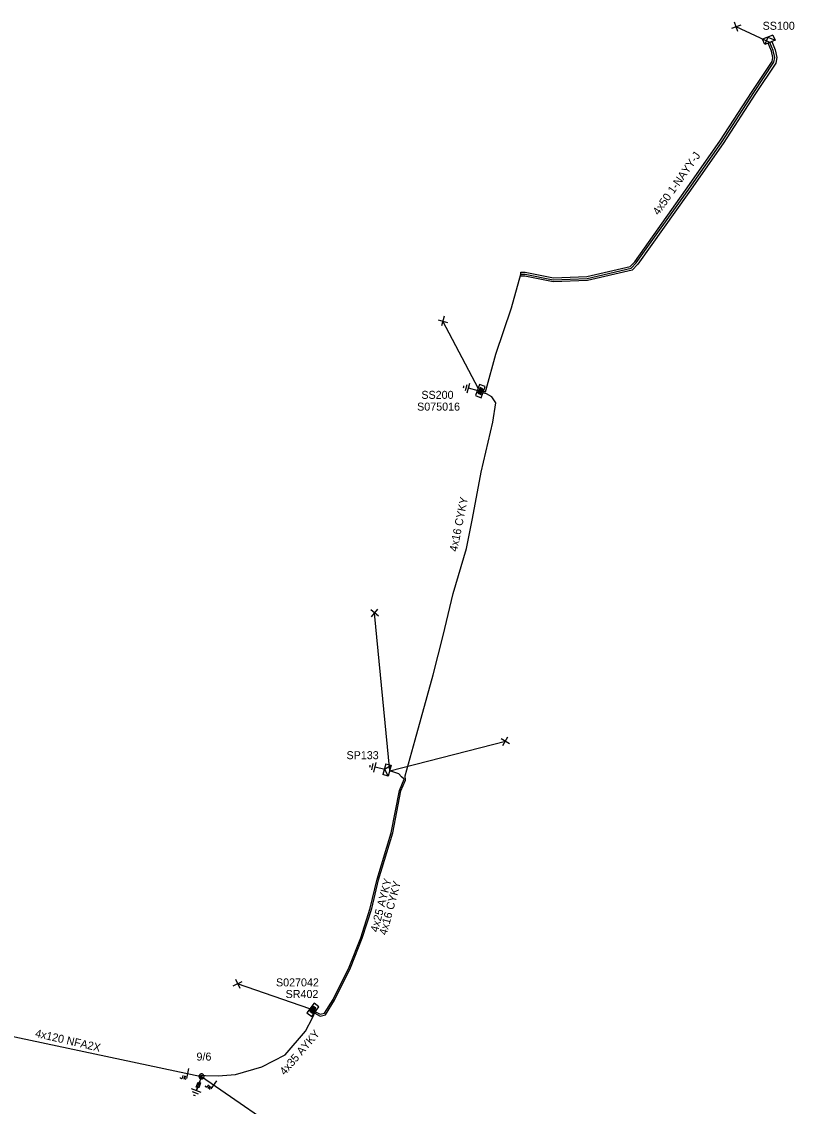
# Model space of a CAD drawing. Extents: x -788458 to -786145, y -1154772 to -1152372.
# Drawn here: x -786269.7 to -786173.2, y -1153537 to -1153401.5 of the extents above; entities that cross this region are included whole.
import ezdxf

# ---------------------------------------------------------------- set-up
doc = ezdxf.new("R2010")
doc.units = 0
for name, color, linetype in [('Vrstva 1', 7, 'Continuous'), ('Vrstva 12', 7, 'Continuous'), ('Vrstva 13', 7, 'Continuous'), ('Vrstva 14', 7, 'Continuous'), ('Vrstva 15', 7, 'Continuous'), ('Vrstva 16', 7, 'Continuous'), ('Vrstva 18', 7, 'Continuous'), ('Vrstva 2', 7, 'Continuous'), ('Vrstva 20', 7, 'Continuous'), ('Vrstva 28', 7, 'Continuous'), ('Vrstva 29', 7, 'Continuous'), ('Vrstva 30', 7, 'Continuous'), ('Vrstva 31', 7, 'Continuous'), ('Vrstva 33', 7, 'Continuous'), ('Vrstva 34', 7, 'Continuous'), ('Vrstva 5', 7, 'Continuous'), ('Vrstva 50', 7, 'Continuous'), ('Vrstva 51', 7, 'Continuous'), ('Vrstva 52', 7, 'Continuous'), ('Vrstva 54', 7, 'Continuous'), ('Vrstva 59', 7, 'Continuous'), ('Vrstva 6', 7, 'Continuous'), ('Vrstva 8', 7, 'Continuous'), ('Vrstva 9', 7, 'Continuous')]:
    doc.layers.add(name, color=color, linetype=linetype)

# ---------------------------------------------------------------- blocks, each defined once
blk = doc.blocks.new('NN440')
at = {"layer": 'Vrstva 2'}
for points in [[(0.63, 0), (0.63, 0.06), (0.62, 0.13), (0.6, 0.19), (0.58, 0.25), (0.55, 0.31), (0.51, 0.37), (0.47, 0.42), (0.42, 0.46), (0.37, 0.51), (0.32, 0.54), (0.26, 0.57), (0.2, 0.59), (0.13, 0.61), (0.07, 0.62), (0, 0.63), (-0.06, 0.62), (-0.13, 0.61), (-0.19, 0.59), (-0.26, 0.57), (-0.31, 0.54), (-0.37, 0.51), (-0.42, 0.46), (-0.47, 0.42), (-0.51, 0.37), (-0.54, 0.31), (-0.57, 0.25), (-0.6, 0.19), (-0.62, 0.13), (-0.63, 0.06), (-0.63, 0), (-0.63, -0.07), (-0.62, -0.14), (-0.6, -0.2), (-0.57, -0.26), (-0.54, -0.32), (-0.51, -0.37), (-0.47, -0.43), (-0.42, -0.47), (-0.37, -0.51), (-0.31, -0.55), (-0.26, -0.58), (-0.19, -0.6), (-0.13, -0.62), (-0.06, -0.63), (0, -0.63), (0.07, -0.63), (0.13, -0.62), (0.2, -0.6), (0.26, -0.58), (0.32, -0.55), (0.37, -0.51), (0.42, -0.47), (0.47, -0.43), (0.51, -0.37), (0.55, -0.32), (0.58, -0.26), (0.6, -0.2), (0.62, -0.14), (0.63, -0.07), (0.63, 0)], [(-0.63, 0), (0.63, 0)], [(-0.6, -0.18), (0.57, -0.18)], [(-0.51, -0.32), (0.5, -0.32)], [(-0.37, -0.47), (0.35, -0.47)]]:
    blk.add_lwpolyline(points, dxfattribs=at)
blk = doc.blocks.new('NN840')
at = {"layer": 'Vrstva 15'}
for points in [[(0, 0.62), (0, -0.63)], [(-0.75, -0.71), (-0.75, -0.66)], [(-0.73, -0.76), (-0.75, -0.71)], [(-0.66, -0.8), (-0.73, -0.76)], [(-0.63, -0.8), (-0.66, -0.8)], [(-0.56, -0.76), (-0.63, -0.8)], [(-0.54, -0.71), (-0.56, -0.76)], [(-0.54, -0.38), (-0.54, -0.71)], [(-0.33, -0.38), (-0.33, -0.8)], [(-0.33, -0.64), (-0.13, -0.38)], [(-0.26, -0.56), (-0.09, -0.8)]]:
    blk.add_lwpolyline(points, dxfattribs=at)
blk = doc.blocks.new('NN800')
at = {"layer": 'Vrstva 1'}
for points in [[(-0.44, 0.44), (0.44, -0.44)], [(-0.44, -0.44), (0.44, 0.44)]]:
    blk.add_lwpolyline(points, dxfattribs=at)
blk = doc.blocks.new('NN820')
at = {"layer": 'Vrstva 13'}
for points in [[(0, 0), (0, -1.05)], [(-0.16, -0.81), (0.16, -0.81)], [(-0.16, -1.47), (-0.16, -0.81)], [(0, -1.05), (-0.06, -0.93)], [(0, -1.05), (0.06, -0.93)], [(0.16, -0.81), (0.16, -1.47)], [(0.16, -1.47), (-0.16, -1.47)], [(0, -1.47), (0, -1.87)]]:
    blk.add_lwpolyline(points, dxfattribs=at)
blk = doc.blocks.new('NN620')
at = {"layer": 'Vrstva 8'}
for points in [[(0.75, 0), (-0.75, 0)], [(-0.75, 0), (-0.75, -0.75)], [(0.75, -0.75), (0.75, 0)], [(-0.75, -0.75), (0.75, -0.75)], [(0.37, -0.18), (-0.38, -0.18)], [(-0.38, -0.18), (-0.38, -0.56)], [(-0.38, -0.56), (0.37, -0.56)], [(0.32, -0.23), (-0.33, -0.23)], [(-0.33, -0.23), (-0.33, -0.51)], [(-0.33, -0.51), (0.32, -0.51)], [(0.27, -0.27), (-0.28, -0.27)], [(-0.28, -0.27), (-0.28, -0.46)], [(-0.28, -0.46), (0.27, -0.46)], [(0.23, -0.32), (-0.23, -0.32)], [(-0.23, -0.32), (-0.23, -0.42)], [(-0.23, -0.42), (0.23, -0.42)], [(-0.19, -0.37), (0.19, -0.37)], [(0.23, -0.42), (0.23, -0.32)], [(0.27, -0.46), (0.27, -0.27)], [(0.32, -0.51), (0.32, -0.23)], [(0.37, -0.56), (0.37, -0.18)]]:
    blk.add_lwpolyline(points, dxfattribs=at)
blk = doc.blocks.new('NN630')
at = {"layer": 'Vrstva 9'}
for points in [[(0, -0.7), (-0.7, 0)], [(-0.7, -0.7), (-0.7, 0), (0.7, 0), (0.7, -0.7)], [(-0.7, -0.7), (0.7, -0.7)], [(0, -0.7), (0.7, 0)]]:
    blk.add_lwpolyline(points, dxfattribs=at)
blk = doc.blocks.new('NN810')
at = {"layer": 'Vrstva 14'}
for points in [[(0, -0.64), (0, -1.89)], [(0.63, -1.89), (-0.62, -1.89)], [(0.39, -2.2), (-0.4, -2.2)], [(0, -2.52), (-0.12, -2.52)], [(0.14, -2.52), (0, -2.52)]]:
    blk.add_lwpolyline(points, dxfattribs=at)

msp = doc.modelspace()

# ---------------------------------------------------------------- linework, layer by layer
at = {"layer": 'Vrstva 20'}
msp.add_lwpolyline([(-786207.37, -1153432.81), (-786206.82, -1153432.83), (-786203.3, -1153433.53), (-786199.12, -1153433.36), (-786193.74, -1153432.11), (-786193.15, -1153431.52), (-786186.81, -1153422.6), (-786182.51, -1153416.47), (-786178.48, -1153410.24), (-786176, -1153406.5), (-786175.91, -1153406.02), (-786176.09, -1153405.23), (-786176.5, -1153404.21), (-786176.04, -1153404.03), (-786175.61, -1153405.07), (-786175.39, -1153406), (-786175.52, -1153406.7), (-786178.06, -1153410.52), (-786182.09, -1153416.75), (-786186.41, -1153422.88), (-786192.77, -1153431.84), (-786193.48, -1153432.57), (-786199.06, -1153433.86), (-786203.34, -1153434.03), (-786206.88, -1153433.33), (-786207.39, -1153433.31)], close=True, dxfattribs=at)
at = {"layer": 'Vrstva 5'}
for points in [[(-786212.05, -1153447.7), (-786211.78, -1153447.79), (-786211.7, -1153447.49), (-786210.5, -1153443.05), (-786208.55, -1153437.3), (-786207.38, -1153433.06), (-786206.85, -1153433.08), (-786203.32, -1153433.78), (-786199.09, -1153433.61), (-786193.61, -1153432.34), (-786192.96, -1153431.68), (-786186.61, -1153422.74), (-786182.3, -1153416.61), (-786178.27, -1153410.38), (-786175.76, -1153406.6), (-786175.65, -1153406.01), (-786175.85, -1153405.15), (-786176.27, -1153404.12)], [(-786233.25, -1153525.16), (-786233.12, -1153525.4), (-786232.45, -1153525.74), (-786231.77, -1153525.58), (-786230.66, -1153523.76), (-786228.65, -1153519.72), (-786227.18, -1153516.02), (-786226, -1153512.31), (-786225.14, -1153508.72), (-786223.38, -1153502.88), (-786222.35, -1153497.62), (-786221.78, -1153496.27), (-786221.81, -1153495.72), (-786220.58, -1153491.25), (-786218.33, -1153483.11), (-786217.07, -1153478.19), (-786215.84, -1153472.98), (-786214.15, -1153467.33), (-786213.4, -1153463.6), (-786212.33, -1153457.81), (-786210.87, -1153451.55), (-786210.5, -1153449.13), (-786211.01, -1153448.38), (-786211.67, -1153448.02), (-786212.11, -1153447.9)], [(-786247.26, -1153533.29), (-786247.3, -1153533.13), (-786246.75, -1153533.16), (-786245.18, -1153533.23), (-786243.03, -1153533.06), (-786239.71, -1153532.1), (-786236.8, -1153530.6), (-786234.28, -1153527.64), (-786233.38, -1153525.95), (-786233.18, -1153525.53), (-786233.33, -1153525.28)]]:
    msp.add_lwpolyline(points, dxfattribs=at)
at = {"layer": 'Vrstva 50'}
msp.add_lwpolyline([(-786381.77, -1153491.03), (-786354.19, -1153499.92), (-786327.4, -1153511.45), (-786300.99, -1153523.12), (-786278.65, -1153526.63), (-786247.26, -1153533.29)], dxfattribs=at)
at = {"layer": 'Vrstva 52'}
for points in [[(-786233.14, -1153525.01), (-786233.04, -1153525.22), (-786232.43, -1153525.52), (-786231.89, -1153525.4), (-786230.84, -1153523.66), (-786228.83, -1153519.64), (-786227.36, -1153515.96), (-786226.2, -1153512.25), (-786225.34, -1153508.66), (-786223.58, -1153502.84), (-786222.55, -1153497.56), (-786221.95, -1153496.16), (-786222.3, -1153495.85), (-786222.62, -1153495.5), (-786223.75, -1153495.1)], [(-786247.26, -1153533.29), (-786223.36, -1153549.79)]]:
    msp.add_lwpolyline(points, dxfattribs=at)
at = {"layer": 'Vrstva 59'}
for points in [[(-786176.27, -1153404.12), (-786180.47, -1153402.18)], [(-786212.68, -1153447.4), (-786217.12, -1153438.94)], [(-786223.75, -1153495.1), (-786225.64, -1153475.4)], [(-786223.75, -1153495.1), (-786209.31, -1153491.4)], [(-786233.72, -1153524.83), (-786242.76, -1153521.7)]]:
    msp.add_lwpolyline(points, dxfattribs=at)

# ---------------------------------------------------------------- block references
at = {"layer": 'Vrstva 13', "xscale": 0.5, "yscale": 0.5, "rotation": -13.03261396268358}
msp.add_blockref('NN440', (-786247.26, -1153533.29), dxfattribs=at)
at = {"layer": 'Vrstva 15'}
for p, rotation in [((-786212.08, -1153447.8), -105.18592123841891), ((-786223.75, -1153495.1), -102.95184169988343), ((-786247.26, -1153533.29), -20.32511953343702)]:
    msp.add_blockref('NN810', p, dxfattribs=dict(at, rotation=rotation))
at = {"layer": 'Vrstva 16', "rotation": -20.232686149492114}
msp.add_blockref('NN820', (-786247.26, -1153533.29), dxfattribs=at)
at = {"layer": 'Vrstva 18'}
for p, rotation in [((-786249, -1153532.92), -11.97871039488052), ((-786245.74, -1153534.33), -34.38640314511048)]:
    msp.add_blockref('NN840', p, dxfattribs=dict(at, rotation=rotation))
at = {"layer": 'Vrstva 28'}
for p, rotation in [((-786212.08, -1153447.8), -109.91744992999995), ((-786233.05, -1153525.19), -126.73676110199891)]:
    msp.add_blockref('NN620', p, dxfattribs=dict(at, rotation=rotation))
at = {"layer": 'Vrstva 31'}
for p, rotation in [((-786176.27, -1153404.12), -157.81598666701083), ((-786223.75, -1153495.1), -105.11347302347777)]:
    msp.add_blockref('NN630', p, dxfattribs=dict(at, rotation=rotation))
at = {"layer": 'Vrstva 34'}
for p, rotation in [((-786180.47, -1153402.18), 155.19003244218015), ((-786217.12, -1153438.94), -60.36664164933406), ((-786225.64, -1153475.4), 95.59203049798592), ((-786209.31, -1153491.4), 14.064263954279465), ((-786242.76, -1153521.7), -19.099891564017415)]:
    msp.add_blockref('NN800', p, dxfattribs=dict(at, rotation=rotation))

# ---------------------------------------------------------------- texts
at = {"layer": 'Vrstva 12'}
msp.add_text('9/6', height=1, dxfattribs=at).set_placement((-786247.89, -1153531.31))
at = {"layer": 'Vrstva 29'}
for s, p in [('S075016', (-786220.33, -1153450.12)), ('S027042', (-786237.96, -1153522.04))]:
    msp.add_text(s, height=1, dxfattribs=at).set_placement(p)
at = {"layer": 'Vrstva 30'}
for s, p in [('SS200', (-786219.8, -1153448.65)), ('SR402', (-786236.76, -1153523.49))]:
    msp.add_text(s, height=1, dxfattribs=at).set_placement(p)
at = {"layer": 'Vrstva 33'}
for s, p in [('SS100', (-786177.18, -1153402.55)), ('SP133', (-786229.15, -1153493.66))]:
    msp.add_text(s, height=1, dxfattribs=at).set_placement(p)
at = {"layer": 'Vrstva 51'}
msp.add_text('4x120 NFA2X', height=1, rotation=346.967, dxfattribs=at).set_placement((-786268.11, -1153528.33))
at = {"layer": 'Vrstva 54'}
msp.add_text('4x25 AYKY', height=1, rotation=75.303, dxfattribs=at).set_placement((-786225.24, -1153515.33))
at = {"layer": 'Vrstva 6'}
for s, rotation, p in [('4x50 1-NAYY-J', 54.889, (-786190.18, -1153425.79)), ('4x16 CYKY', 78.631, (-786215.34, -1153467.8)), ('4x16 CYKY', 74.849, (-786224.15, -1153515.71)), ('4x35 AYKY', 49.591, (-786236.85, -1153533.21))]:
    msp.add_text(s, height=1, rotation=rotation, dxfattribs=at).set_placement(p)

doc.saveas('drawing.dxf')
